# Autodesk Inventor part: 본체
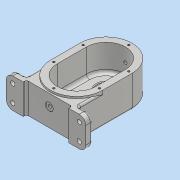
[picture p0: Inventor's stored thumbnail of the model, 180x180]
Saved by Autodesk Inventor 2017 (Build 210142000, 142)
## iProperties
Part Number: 본체
Material: 알루미늄 6061
Document SubType Name: Modeling
Designer: MRC
Density: 2.7 g/cm^3
Appearance: 알루미늄 - 평지
Mass: 756.754 g
Surface Area: 581.829 cm^2
Volume: 280.279 cm^3
Author: MRC
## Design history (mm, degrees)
sketch "스케치1"
  geometry: L1 (0, 0)-(0, -45); L2 (-40, 0)-(-40, -45); L3 (40, -45)-(40, 0); A1 r 40 centre (0, 0) between (40, 0) and (-40, 0); A2 r 40 centre (0, -45) between (-40, -45) and (40, -45); 1 further point
  constraints: 8 end point, 4 point on circle, 4 tangent, 2 centre point, 1 midpoint, 1 parallel, 1 vertical
  dimensions: "d0" = 45 distance of L1.start L1.end; "d1" = 80 diameter of A2
extrude "돌출1" new body sketch "스케치1" distance "d2" = 21; taper "d4" = 0 deg; dims "d3" = 28, "d5" = 0
sketch "스케치2"
  geometry: L1 (0, 0)-(0, -45); L2 (-30, 0)-(-30, -45); L3 (30, -45)-(30, 0); A1 r 40 centre (0, -45) between (-40, -45) and (40, -45) reference; A2 r 40 centre (0, 0) between (40, 0) and (-40, 0) reference; A3 r 30 centre (0, 0) between (30, 0) and (-30, 0); A4 r 30 centre (0, -45) between (-30, -45) and (30, -45); 1 further point
  constraints: 8 end point, 4 point on circle, 4 tangent, 2 centre point, 1 midpoint, 1 parallel, 1 vertical
  dimensions: "d6" = 30 radius of A3
extrude "돌출2" cut sketch "스케치2" distance "d7" = 41; taper "d8" = 0 deg
sketch "스케치3"
  geometry: L1 (0, 0)-(0, -45); L2 (-26, 0)-(-26, -45); L3 (26, -45)-(26, 0); A1 r 40 centre (0, 0) between (40, 0) and (-40, 0) reference; A2 r 40 centre (0, -45) between (-40, -45) and (40, -45) reference; A3 r 26 centre (0, 0) between (26, 0) and (-26, 0); A4 r 26 centre (0, -45) between (-26, -45) and (26, -45); 1 further point
  constraints: 8 end point, 4 point on circle, 4 tangent, 2 centre point, 1 midpoint, 1 parallel, 1 vertical
  dimensions: "d9" = 52 diameter of A4
extrude "돌출3" join sketch "스케치3" distance "d10" = 11; taper "d11" = 0 deg
sketch "스케치4"
  geometry: L1 (-26, 0)-(-26, -45) reference; L2 (26, -45)-(26, 0) reference; L3 (-26, -30)-(26, -30); A1 r 26 centre (0, 0) between (26, 0) and (-26, 0) reference
  constraints: 2 end point, 2 point on line, 1 perpendicular
  dimensions: "d12" = 30 distance from line of A1.centre L3
extrude "돌출4" cut sketch "스케치4" distance "d13" = 3; taper "d14" = 0 deg
hole "구멍1" diameter "d17" = 22; stored, may be unused: countersink angle "d21" = 90 deg, drill point angle "d23" = 118 deg; dims "d15" = 10, "d16" = 10, "d18" = 6, "d19" = 28, "d20" = 8, "d22" = 8
sketch "스케치5"
  geometry: C1 r 11 at (0, 0) reference; C2 r 14 at (0, 0); A1 r 26 centre (0, 0) between (26, 0) and (-26, 0) reference
  constraints: 1 centre point, 1 coincident
  dimensions: "d24" = 28 diameter of C2
extrude "돌출5" cut sketch "스케치5" distance "d25" = 4; taper "d26" = 0 deg
hole "구멍2" diameter "d32" = 20; stored, may be unused: countersink angle "d36" = 90 deg, drill point angle "d38" = 0 deg; dims "d30" = 10, "d31" = 10, "d33" = 6, "d34" = 28, "d35" = 8, "d37" = 12
fillet "모깎기1" dims "d39" = 3
fillet "모깎기2" dims "d40" = 0.3
chamfer "모따기2" distance "d41" = 1; stored, may be unused: second distance "d42" = 2, angle "d43" = 45 deg
sketch "스케치6"
  geometry: L1 (-40, 0)-(-40, -45) reference; L2 (-40, -45)-(-40, -82); L3 (-40, -82)-(-61, -82); L4 (-61, -82)-(-61, -92); L5 (-61, -92)-(61, -92); L6 (61, -92)-(61, -82); L7 (61, -82)-(40, -82); L8 (-40, -82)-(-40, -45); L9 (40, -45)-(40, -82); A1 r 26 centre (0, 0) between (26, 0) and (-26, 0) reference; A2 r 40 centre (0, -45) between (-40, -45) and (40, -45) reference; A3 r 40 centre (0, -45) between (-40, -45) and (40, -45) reference; 1 further point
  constraints: 16 end point, 5 perpendicular, 5 tangent, 3 point on line, 1 collinear, 1 midpoint, 1 vertical, 1 vertical alignment
  dimensions: "d44" = 10 distance of L5.end L6.end; "d45" = 92 distance from line of L5 A1.centre; "d46" = 122 distance of L4.end L5.end
extrude "돌출6" join sketch "스케치6" distance "d47" = 46; taper "d48" = 0 deg
sketch "스케치7"
  geometry: L1 (-61, -92)-(61, -92) reference; L2 (-35, -87)-(35, -87); L3 (35, -87)-(35, -92); L4 (35, -92)-(-35, -92); L5 (-35, -92)-(-35, -87); 1 further point
  constraints: 8 end point, 2 midpoint, 2 parallel, 1 horizontal, 1 perpendicular
  dimensions: "d49" = 70 distance of L3.end L4.end; "d50" = 5 distance of L2.end L3.end
extrude "돌출7" cut sketch "스케치7" stored distance "d51" = 46; taper "d52" = 0 deg
sketch "스케치10"
  geometry: A1 r 26 centre (0, 0) between (26, 0) and (-26, 0) reference; 1 further point
  constraints: 1 vertical alignment
  dimensions: "d75" = 20 distance of A1.centre point (0, 20)
hole "구멍5" sketch "스케치10" at (0, 20) diameter "d76" = 3.242; stored, may be unused: countersink angle "d80" = 90 deg, drill point angle "d82" = 118 deg; dims "d77" = 8, "d78" = 28, "d79" = 8, "d81" = 10
fillet "모깎기3" dims "d86" = 10
sketch "스케치11"
  geometry: A1 r 10 centre (-11, 10) between (-21, 10) and (-11, 0) reference; A2 r 10 centre (-11, 36) between (-11, 46) and (-21, 36) reference; 3 further points
  constraints: 2 coincident
hole "구멍6" sketch "스케치11" at (-11, 36), (-11, 10) diameter "d87" = 6.6; stored, may be unused: countersink angle "d91" = 90 deg, drill point angle "d93" = 118 deg; dims "d88" = 8, "d89" = 11, "d90" = 2, "d92" = 10
fillet "모깎기4" dims "d94" = 3
node "작업 평면1"
sketch "스케치12"
  geometry: C1 r 6 at (35, 28); 1 further point
  constraints: 1 centre point, 1 coincident
  dimensions: "d96" = 12 diameter of C1
extrude "돌출8" join sketch "스케치12" stored distance "d97" = 46; taper "d98" = 0 deg
hole "구멍7" diameter "d101" = 4.917; stored, may be unused: countersink angle "d105" = 90 deg, drill point angle "d107" = 118 deg; dims "d99" = 10, "d100" = 10, "d102" = 12, "d103" = 11, "d104" = 2, "d106" = 17.1
sketch "스케치14"
  geometry: L1 (-51, -92)-(-35, -92) reference; L2 (-32, -87)-(32, -87) reference; 2 further points
  constraints: 1 midpoint, 1 vertical alignment, 1 other
  dimensions: "d126" = 12 distance from line of point (0, -80) L1
feature "엠보싱1" sketch "스케치14" dims "d0" = 45, "d1" = 80, "d127" = 0.5, "d128" = 0
sketch "스케치16"
  geometry: C1 r 14 at (0, -45) reference; 7 further points
hole "구멍10" sketch "스케치16" at (0, 35), (0, -80), (-35, 0), (35, 0), (-35, -45), (35, -45) diameter "d132" = 3.242; stored, may be unused: countersink angle "d136" = 90 deg, drill point angle "d138" = 118 deg; dims "d133" = 8, "d134" = 4, "d135" = 2, "d137" = 10
sketch "스케치17"
  geometry: L1 (72, 49)-(-8, 49) reference; 2 further points
  constraints: 1 coincident
  dimensions: "d139" = 21 distance from line of point (32, 28) L1
hole "구멍11" sketch "스케치17" at (32, 28) diameter "d140" = 4.917; stored, may be unused: countersink angle "d144" = 90 deg, drill point angle "d146" = 0 deg; dims "d141" = 12, "d142" = 12, "d143" = 1, "d145" = 17.1
fillet "모깎기5" dims "d147" = 3
fillet "모깎기6" dims "d148" = 5
node "솔리드1"
pattern_circular "원형 패턴3" dims angle "d84" = 360 deg
mirror "미러1"
other parameters: "d95" = -135
